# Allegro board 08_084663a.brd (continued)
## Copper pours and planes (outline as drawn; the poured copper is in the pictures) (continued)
VIN on LAYER3_PWR: 47.37,121.16 55.37,121.16 55.37,111.25 29.34,111.25 29.34,88.9 58.67,88.9 58.67,27.05 84.2,27.05 84.2,17.65 81.79,17.65 81.79,21.08 58.67,21.08 58.67,2.92 16.26,2.92 16.26,10.67 53.09,10.67 53.09,82.68 12.19,82.68 12.19,88.9 21.08,88.9 21.08,116.84 47.37,116.84
_N38 on BOTTOM: 50.04,49.4 50.04,56.26 51.69,56.26 51.69,49.4
_N119 on TOP: 29.08,100.84 29.08,100.08 31.24,100.08 32,99.31 32,96.9 35.05,96.9 35.05,100.84
_N125 on TOP: 35.56,100.46 35.56,96.52 36.96,96.52 36.96,100.46
_N127 on TOP: 31.75,106.68 31.75,101.09 38.73,101.09 38.73,98.68 59.05,98.68 59.05,102.87 42.8,102.87 42.8,106.55 42.67,106.68
_N127 on BOTTOM: 38.48,106.93 38.48,105.16 43.31,105.16 43.31,108.71 42.04,108.71 42.04,107.44 41.53,106.93
_N134 on TOP: 72.52,107.82 72.52,85.34 47.75,85.34 47.75,95.25 69.22,95.25 69.22,105.16 61.09,105.16 61.09,107.82
_N135 on TOP: 33.15,88.65 42.54,88.65 42.54,80.65 86.28,80.65 86.28,73.28 66.42,73.28 66.42,71.25 33.15,71.25
_N230 on BOTTOM: 106.05,21.21 106.05,14.22 112.14,14.22 112.14,21.21
_N232 on BOTTOM: 112.27,24.89 112.27,31.62 106.05,31.62 106.05,24.89
DRAINB_1 on TOP: 45.59,36.96 45.59,54.23 43.81,54.23 43.81,56.9 60.07,56.9 60.07,55.5 52.83,55.5 52.2,54.86 52.2,36.96
DRAINB_1 on BOTTOM: 46.1,42.42 46.1,26.16 102.11,26.16 102.11,37.59 120.4,37.59 120.4,25.02 126.11,25.02 126.11,42.42 97.92,42.42 97.92,29.84 51.69,29.84 51.69,42.42
DRAINB_2 on TOP: 45.59,4.06 45.59,21.34 43.81,21.34 43.81,24 60.07,24 60.07,22.61 52.2,22.61 52.2,4.06
DRAINB_2 on BOTTOM: 120.52,8 120.52,20.57 126.11,20.57 126.11,4.06 46.36,4.06 46.36,8 46.35,8 46.35,9.91 51.82,9.91 51.82,8
HV_RAIL on TOP: 61.91,61.92 61.91,22.31 68.69,22.31 68.7,22.31 68.71,22.32 68.71,44.95 68.72,44.96 131.56,44.96 131.57,44.97 131.57,51.94 131.56,51.94 101.98,51.94 101.98,51.95 101.98,55.12 100.2,55.12 100.2,51.95 100.2,51.94 68.71,51.94 68.71,51.95 68.71,61.91 68.7,61.92
OUT on TOP: 87.12,10.16 87.12,12.19 74.55,12.19 74.55,10.16
VOUT1 on TOP: 63.88,111 63.88,127 61.09,127 61.09,111
VOUT1 on TOP: 5.71,102.36 5.71,105.92 7.11,105.92 7.11,102.36
VOUT1 on BOTTOM: 44.2,101.6 68.71,101.6 68.71,114.3 44.2,114.3
VOUT1 on BOTTOM: 14.99,93.73 14.99,91.57 17.53,91.57 17.53,92.71 16.38,92.71 16.38,93.73
VOUT1 on LAYER3_PWR: 0.51,131.57 64.77,131.57 64.77,107.06 68.45,107.06 68.45,101.47 42.54,101.47 42.54,107.95 60.71,107.95 60.71,128.14 45.97,128.14 45.97,117.73 17.27,117.73 17.27,91.31 0.51,91.31
VOUT_240V on TOP: 99.06,131.56 99.07,131.57 115.19,131.57 115.19,98.3 131.57,98.3 131.57,57.06 131.56,57.02 131.52,57.01 80.37,57.01 80.36,57.02 80.36,70.99 86.05,70.99 86.05,63.32 86.06,63.31 99.06,63.31 99.06,63.31

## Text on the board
Ref Des/Silkscreen Bottom: 1 | VDDB_INPUT | VDD1_INPUT | P6
User.Comments: 4.    INSTALL M033288 ON BELOW COMPONENTS | 5.    OVERLAPPING COMPONENTS: | P9:PIN2 AND PIN3 | P2:PIN2 AND PIN3 | P8:PIN1 AND PIN2 | P1:PIN1 AND PIN2 | -C34 & COUT11 | -L1 & L7 | -L2 & L5
Ref Des/Assembly Top: 1
Ref Des/Silkscreen Top: DIS | EN | ADUM4221-1 | LTC7840 | HV | P2 | P9 | REF DES | P8 | P1 | JP1 | ON | 1-2 | 2-3 | MAX20076D | JUMPER TABLE: | OPEN | OFF | 5V OUT | EVAL BRD Z | IC | U3 | U4 | U1 | U2 | U2 MODE | * | GND | VIN=9V-36V | 48V | HIGH VOLTAGE DC-AC H-BRIDGE DRIVER | VOUT240V | RUN U1 | 1 | NOTPWM | PWM | HV BUS | 240V/0.7A | HB OUT
DIMENSION: FAB NOTES REVISION: NOVEMBER 21 2022 | 8.   IMPEDANCE REQUIREMENTS: IF NO STACKUP IS DEFINED, THE VENDOR IS ALLOWED TO ADJUST THE DIELECTRIC | 13.  PLATING SPECIFICATION: | 1.   DIMENSIONS ARE IN INCHES (EXCEPT WHERE NOTED). | ALL DOCUMENTS & SPECIFICATIONS REFERRED TO BELOW SHOULD BE THE LATEST REVISIONS. | 2.  BOARD MATERIAL:(USE CHECKED ITEMS) | 3.   ALL LAMINATES & BONDING MATERIALS SHOULD BE SELECTED FROM IPC-4101 OR IPC-4103,(TG>170 DEGC TD>300 DEGC) | 4.   REFER TO IPC-6010 SERIES, CLASS 2 FOR FABRICATION. | 5.   REFER TO LAMINATION DIAGRAM FOR OVERALL BOARD THICKNESS, TOLERANCE APPLIES AFTER ALL LAMINATION AND PLATING | 6.   BOW & TWIST NOT TO EXCEED 0.0075 INCHES (0.75%) PER LINEAR INCH AND SHOULD BE MEASURED PER IPC-TM-650, METHOD 2.4.22. | 7.   ACCEPTABILITY PER ADI SPECIFICATION TST00115. | 9.   FILLET OPTIONS TO ENHANCE RELIABILITY AT PAD JUNCTIONS WHERE SPACING PERMITS. | 10.  THIEVING: | 11.  LAYER TO LAYER REGISTRATION SHALL BE WITHIN 0.003 INCHES. | 12.  DRILL SIZES ARE FINISHED HOLE SIZES. ALL HOLES SHALL BE LOCATED WITHIN 0.005 INCHES DTP, | 14.  SURFACE FINISH: | 15.  SOLDERMASK: | 16.  APPLY SILKSCREEN TO BOTH SIDES USING A NON-CONDUCTIVE, EPOXY BASED INK PER ARTWORK. | (X) WHITE | ( ) OTHER | PROCESSES. FINISHED THICKNESS MEASURED FROM TOP COPPER TO BOTTOM COPPER. | (X)  ISOLA 370HR OR EQUIVALENT | ( )  ISOLA-FR408HR OR EQUIVALENT | ( )  ISOLA IS410 | ( )  MEGTRON 6 | ( )  NELCO-4000-13 | ( )  ROGERS 4350B | ( ) ROGERS 3003 | ( ) ARLON 85N | ( ) EM370D | ( )  OTHER ________________________ | ( ) FILLETS ALLOWED | (X) FILLETS NOT ALLOWED | ( ) VENDOR MAY ADD THIEVING TO COMPENSATE FOR LOW COPPER DENSITY AREAS MAINTAINING A MINIMUM | ( ) VENDOR MAY NOT ADD THIEVING TO COMPENSATE FOR LOW COPPER DENSITY AREAS. | (X) LPI | ( ) OTHER_________ | COLOR | (X) GREEN | HINDER PROPER SOLDER WICKING. BARREL RELIEF ON SOLDERMASK ALLOWED IN UNFILLED VIA IN PAD HOLES. | (X) REFER TO LAMINATION DIAGRAM FOR FINISHED COPPER WEIGHT/THICKNESS REQUIRMENTS | (X) IMMERSION GOLD (ENIG) 1.58-3.94 MICRO INCHES OVER 118-236 MICRO INCHES MIN. OF ELECTROLESS NICKEL PER IPC-4552 | ( ) OSP (ORGANIC SOLDERABILITY PRESERVATIVE) | ( ) IMMERSION SILVER | ( ) SOFT WIRE BONDABLE GOLD 30-50 MICRO INCHES OF SOFT WIRE | ( ) EDGE CONNECTOR FINGERS ARE TO BE PLATED WITH 100 MICRO-INCHES(.0001") OF LOW STRESS | THICKNESS & TRACE WIDTHS TO MEET THE IMPEDANCE REQUIREMENT. IF SPECIFIED, THE VENDOR MUST | TRACE WIDTH & SPACING THAT IMPACT THE REQUIREMENTS MUST HAVE WRITTEN APPROVAL FROM ADI. | MINIMUM BARREL PLATING OF 0.001 INCHES. PLATED HOLES SHALL NOT BE ROUGH OR IRREGULAR SO AS TO | SOLDERMASK OVER BARE COPPER OR BARE GOLD (BOTH SIDES) TO MEET IPC-SM-840. | IF PRESENT,DO NOT MODIFY SOLDERMASK DEFINED PADS (MASK OPENINGS LESS THAN COPPER PAD) WITHOUT APPROVAL. | MEET THE REQUIREMENTS LISTED IN THE IMPEDANCE TABLE. ANY ADJUSTMENT MADE TO THE DEFINED STACKUP, | UL FLAMMABILITY RATING 94V-0. BOARD MATERIAL & CONSTRUCTION SHALL MEET THE REQUIREMENTS OF UL796/UL796F. | BONDABLE GOLD OVER 100-150 MICRO INCHES OF NICKEL | NICKEL UNDER 30 MICRO-INCHES (.00003') OF GOLD | 0.100 INCH CLEARANCE FROM ALL COPPER FEATURES, | THE STARTING COPPER WEIGHT/THICKNESS CAN VARY AS LONG AS THE FINISHED COPPER | WEIGHT/THICKNESS IS NOT LESS THAN THE SPECIFIED VALUE. | UNLESS OTHERWISE SPECIFIED | HOMOGENOUS MATERIALS IN THIS BOARD SHALL BE COMPLAINT WITH THE EU DIRECTIVE 2002/95/EC | WORKMANSHIP SHALL CONFORM TO IPC-A-600, CLASS 2. | 21.  INTENTIONAL SHORTS: | 17.  FINAL ELECTRICAL TEST TO BE PERFORMED USING PROVIDED IPC-D-356A NETLIST OR ODB++ FORMAT FILE. | 22.  PEMNUTS: | 23.  MANUFACTURER TO ETCH/STAMP WITH PERMANENT NON-CONDUCTIVE INK | ON SECONDARY SIDE UNLESS OTHERWISE SPECIFIED: | 18.  A TIME DOMAIN REFLECTOMETER REPORT (TDR) FOR EACH IMPEDANCE CONTROLLED LAYER & A CERTIFICATE | 19.  IF PRESENT, ALL BLIND/BURIED VIAS WITH AN ASPECT RATIO <1:1 TO BE PLATED SHUT WITH COPPER WHEN | 20.  FOR VIA FILL INFORMATION REFER TO DRILL CHART: | 24. PANELIZATION: | 25.  MINIMUM DESIGN LINE WIDTH IS 0.008 INCH | 26.  MINIMUM DESIGN LINE SPACING IS 0.008 INCH | IS ACCEPTABLE, ALL OTHER INSTANCES MUST BE REPORTED. | IF AN INTENTIONAL SHORT REPORT IS SUPPLIED AND DOES NOT MATCH THE FAB DATA THEN | THE PCB SHALL HAVE A VERIFICATION STAMP. | (X)  NON-CONDUCTIVE EPOXY FILL ALL 0.1001 INCHES DRILLED VIAS | ()COPPERFILL ALL 0.000 INCHES DRILLED VIAS | ( ) PEMNUTS TO BE INSTALLED BY FABRICATOR | ( ) PEMNUTS NOT TO BE INSTALLED BY FABRICATOR | ( ) NOT APPLICABLE | USED AS VIA-IN-PAD OR AS A STACKED VIA. BLIND/BURIED VIAS WITH AN ASPECT RATIO >1:1 TO BE FILLED | A. UL CODE-FLAMMABILITY RATING FOR THOSE APPROVED MATERIALS(IF APPLICABLE) | B. DATE CODE | C. LOT NUMBER | D. MANUFACTURER LOGO | BOARDS TO BE SHIPPED IN SINGULATED AFTER FABRICATION PROCESS | SMOOTHEN EDGES AND FREE FROM BURRS AFTER DEPANELIZATION | CAN'T BE PERFORMED BECAUSE THE TRACE LENGTH IS TOO SHORT ON THE OUTER LAYERS AT THE PIN ESCAPES | ADI APPROVAL IS REQUIRED. | OF COMPLIANCE SHALL BE PROVIDED BY VENDOR AT TIME OF SHIPMENT. INSTANCES WHERE TDR TESTING | WITH NON-CONDUCTIVE EPOXY. | DIA MAX,SEE NOTE 20 | REF | DIA MAX | NOTES: | TOOLING: | FINISH: | MATERIAL: | TESTING: | MISCELLANEOUS:
PAGE_OUTLINE: TEST PROCESS | N/A | LABEL PLACEMENT INFORMATION | HALF SIZE LABELS ARE | AVAILABLE IN THE LIBRARY | PLACE WHEELIE BIN LOGO | TO SUIT THE LAYOUT. | PLACE ROHS COMPLIANT LOGO | TO SUIT THE LAYOUT OR | DELETE IF NOT REQ'D. | PLACE CHINA ROHS COMPLIANT | LOGO TO SUIT THE LAYOUT OR | 1.THE BOARD SIZE CAN BE ADJUSTED TO SUIT THE APPLICATION. | 2.THE MOUNTING HOLES CAN BE MOVED/REMOVED TO SUIT THE APPLICATION. | 3.THE FIDUCIALS CAN BE MOVED TO SUIT THE APPLICATION. | 4.ADJUST THE DIMENSIONS TO SUIT THE APPLICATION. | 5.ADD THE CORRECT LAYER STACKUP ON FAB2 BASED ON THE NO OF LAYERS ON THE PCB. | 6.THE ROHS COMPLIANT AND WHEELIE BIN LOGO'S CAN BE MOVED TO THE DESIRED LOCATION. | HALF SIZE VERSIONS OF THE LABELS ARE AVAILABLE IN THE LIBRARY. | NOTES FOR TEMPLATE USAGE. | GENERIC D-SIZE TEMPLATE BR-067706A
User.11: see Assy detail A | see Assy detail B
User.22: 08-      -07 | LAYER2 GND
User.23: LAYER3 PWR | 08-      -08
User.45: FIGURE | SIZE | 10.0 | 10.01 | 20.0 | 35.0 | 45.0 | 50.0 | 70.0 | 100.0 | 213.0 | 125.0 | PLATED | NON-PLATED | DRILL CHART: TOP to BOTTOM | ALL UNITS ARE IN MILS | QTY | 603 | 35 | 10 | 12 | 2 | 41 | 5 | 4 | 718 | TOLERANCE/NOTES | TOTAL HOLES:
